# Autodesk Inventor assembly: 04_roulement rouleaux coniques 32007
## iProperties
Shininess: 60.0
Length Units: 11270
Angle Units: 11279
Time Units: 11290
Mass Units: 11283
Length Display Precision: 3
Angle Display Precision: 2
Created: 2000-10
Part Number: 04_roulement rouleaux coniques 32007
Document SubType Name: Assemblage
Density: 0.0
Volumn: 0.0
Area: 0.0
PropertySet Name: Model Information
Control State: 0
Master: False
Checked Out: False
Author: Laurent GAUTHERON
